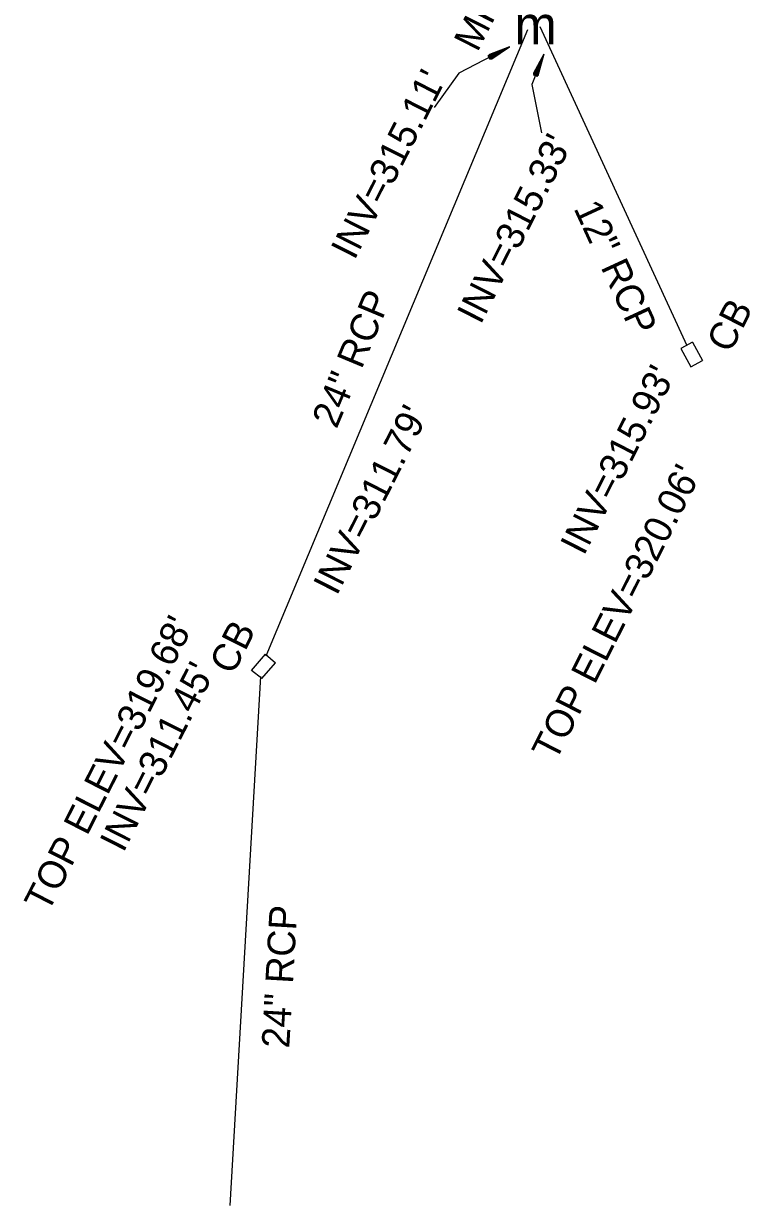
# Model space of a CAD drawing. Extents: x 1975859 to 1978323, y 778892 to 782836.
# Drawn here: x 1978070.4 to 1978175.3, y 782452.2 to 782622.9 of the extents above; entities that cross this region are included whole.
import ezdxf

# ---------------------------------------------------------------- set-up
doc = ezdxf.new("R2010")
doc.units = 0
for name, color, linetype in [('Exist Structure Minor Catch Basin', 7, 'Continuous'), ('Exist Structure Minor Catch Basin Text', 7, 'Continuous'), ('Exist Structure Minor Catch Basin Top Elevation', 7, 'Continuous'), ('Exist Structure Minor Pipes RCP 12 Inch', 7, 'Continuous'), ('Exist Structure Minor Pipes RCP 12 Inch Text', 7, 'Continuous'), ('Exist Structure Minor Pipes RCP 15 Inch Invert', 7, 'Continuous'), ('Exist Structure Minor Pipes RCP 24 Inch', 7, 'Continuous'), ('Exist Structure Minor Pipes RCP 24 Inch Invert', 7, 'Continuous'), ('Exist Structure Minor Pipes RCP 24 Inch Text', 7, 'Continuous'), ('Exist Structure Minor Storm Sewer Manhole CELL', 7, 'Continuous'), ('Exist Structure Minor Storm Sewer Manhole Text', 7, 'Continuous')]:
    doc.layers.add(name, color=color, linetype=linetype)

msp = doc.modelspace()

# ---------------------------------------------------------------- linework, layer by layer
at = {"layer": 'Exist Structure Minor Catch Basin'}
for p, q in [((1978167.01, 782576.9), (1978168.42, 782574.24)), ((1978104.79, 782528.33), (1978106.75, 782530.57))]:
    msp.add_line(p, q, dxfattribs=at)
for points in [[(1978166.97, 782576.86), (1978167.01, 782576.9), (1978165.3, 782575.99), (1978166.76, 782573.3), (1978168.42, 782574.24)], [(1978104.79, 782528.33), (1978103.31, 782529.46), (1978105.33, 782531.84), (1978106.75, 782530.57)]]:
    msp.add_lwpolyline(points, dxfattribs=at)
at = {"layer": 'Exist Structure Minor Pipes RCP 12 Inch'}
msp.add_line((1978144.94, 782622.47), (1978166.17, 782576.41), dxfattribs=at)
at = {"layer": 'Exist Structure Minor Pipes RCP 15 Inch Invert'}
for p, q in [((1978145.51, 782618.45), (1978143.81, 782614.09)), ((1978144.55, 782615.27), (1978144.06, 782615.46)), ((1978144.12, 782615.49), (1978144.42, 782615.66)), ((1978144.42, 782615.66), (1978144.17, 782615.42)), ((1978144.42, 782615.66), (1978144.25, 782615.38)), ((1978144.42, 782615.66), (1978144.36, 782615.34)), ((1978144.42, 782615.66), (1978144.52, 782615.33)), ((1978144.42, 782615.66), (1978144.46, 782615.3)), ((1978143.81, 782614.09), (1978145.18, 782607.13))]:
    msp.add_line(p, q, dxfattribs=at)
for points in [[(1978144.55, 782615.27), (1978144.72, 782615.45), (1978145.51, 782618.45), (1978144.05, 782615.71), (1978144.06, 782615.46)], [(1978144.55, 782615.43), (1978145.51, 782618.45), (1978144.55, 782615.27), (1978144.52, 782615.33), (1978144.55, 782615.43), (1978144.42, 782615.66), (1978144.16, 782615.58), (1978144.12, 782615.49), (1978144.06, 782615.46), (1978145.51, 782618.45), (1978144.16, 782615.58)], [(1978144.06, 782615.59), (1978145.51, 782618.45), (1978144.64, 782615.36)], [(1978145.44, 782618.3), (1978145.48, 782618.37), (1978145.46, 782618.27), (1978145.43, 782618.18), (1978145.44, 782618.28), (1978145.4, 782618.21), (1978145.36, 782618.12), (1978145.41, 782618.19), (1978145.4, 782618.1), (1978145.37, 782618.01), (1978145.38, 782618.1), (1978145.32, 782618.04), (1978145.28, 782617.96), (1978145.34, 782618.02), (1978145.34, 782617.92), (1978145.31, 782617.83), (1978145.31, 782617.93), (1978145.24, 782617.87), (1978145.2, 782617.79), (1978145.27, 782617.84), (1978145.29, 782617.74), (1978145.26, 782617.65), (1978145.24, 782617.75), (1978145.16, 782617.7), (1978145.12, 782617.62), (1978145.21, 782617.67), (1978145.23, 782617.56), (1978145.2, 782617.47), (1978145.17, 782617.58), (1978145.08, 782617.53), (1978145.04, 782617.45), (1978145.14, 782617.49), (1978145.17, 782617.38), (1978145.14, 782617.29), (1978145.1, 782617.41), (1978145, 782617.36), (1978144.96, 782617.28), (1978145.07, 782617.32), (1978145.12, 782617.2), (1978145.09, 782617.11), (1978145.03, 782617.23), (1978144.92, 782617.19), (1978144.88, 782617.11), (1978145, 782617.14), (1978145.06, 782617.03), (1978145.03, 782616.94), (1978144.97, 782617.06), (1978144.84, 782617.02), (1978144.8, 782616.94), (1978144.93, 782616.97), (1978145, 782616.85), (1978144.97, 782616.76), (1978144.9, 782616.88), (1978144.76, 782616.85), (1978144.72, 782616.77), (1978144.86, 782616.8), (1978144.95, 782616.67), (1978144.92, 782616.58), (1978144.83, 782616.71), (1978144.68, 782616.69), (1978144.64, 782616.6), (1978144.8, 782616.62), (1978144.89, 782616.49), (1978144.86, 782616.4), (1978144.76, 782616.53), (1978144.6, 782616.52), (1978144.56, 782616.43), (1978144.73, 782616.45), (1978144.83, 782616.31), (1978144.8, 782616.22), (1978144.7, 782616.36), (1978144.52, 782616.35), (1978144.48, 782616.26), (1978144.66, 782616.27), (1978144.78, 782616.13), (1978144.75, 782616.04), (1978144.63, 782616.19), (1978144.44, 782616.18), (1978144.4, 782616.09), (1978144.59, 782616.1), (1978144.72, 782615.95), (1978144.69, 782615.86), (1978144.56, 782616.01), (1978144.36, 782616.01), (1978144.32, 782615.92), (1978144.52, 782615.92), (1978144.66, 782615.78), (1978144.63, 782615.69), (1978144.49, 782615.84), (1978144.28, 782615.84), (1978144.24, 782615.75), (1978144.46, 782615.75), (1978144.61, 782615.6), (1978144.58, 782615.51), (1978144.42, 782615.66), (1978144.2, 782615.67)]]:
    msp.add_lwpolyline(points, dxfattribs=at)
at = {"layer": 'Exist Structure Minor Pipes RCP 24 Inch'}
for p, q in [((1978105.41, 782531.58), (1978143.2, 782622.04)), ((1978100.23, 782452.23), (1978104.64, 782528.59))]:
    msp.add_line(p, q, dxfattribs=at)
at = {"layer": 'Exist Structure Minor Pipes RCP 24 Inch Invert'}
for p, q in [((1978140.57, 782619.53), (1978133.25, 782615.75)), ((1978137.74, 782617.77), (1978137.5, 782618.24)), ((1978137.91, 782618.15), (1978137.55, 782618.14)), ((1978137.56, 782618.22), (1978137.91, 782618.15)), ((1978137.91, 782618.15), (1978137.59, 782618.06)), ((1978137.91, 782618.15), (1978137.65, 782617.95)), ((1978137.91, 782618.15), (1978137.7, 782617.86)), ((1978137.91, 782618.15), (1978137.76, 782617.83)), ((1978133.25, 782615.75), (1978129.7, 782610.75))]:
    msp.add_line(p, q, dxfattribs=at)
for points in [[(1978137.85, 782617.89), (1978140.57, 782619.53), (1978137.74, 782617.77), (1978137.76, 782617.83), (1978137.85, 782617.89), (1978137.91, 782618.15), (1978137.66, 782618.26), (1978137.56, 782618.22), (1978137.5, 782618.24), (1978140.57, 782619.53), (1978137.66, 782618.26)], [(1978137.74, 782617.77), (1978137.99, 782617.79), (1978140.57, 782619.53), (1978137.66, 782618.43), (1978137.5, 782618.24)], [(1978137.58, 782618.34), (1978140.57, 782619.53), (1978137.87, 782617.78)], [(1978140.41, 782619.45), (1978140.48, 782619.48), (1978140.41, 782619.43), (1978140.33, 782619.38), (1978140.4, 782619.44), (1978140.32, 782619.42), (1978140.24, 782619.38), (1978140.32, 782619.4), (1978140.25, 782619.33), (1978140.17, 782619.28), (1978140.24, 782619.35), (1978140.15, 782619.34), (1978140.07, 782619.31), (1978140.15, 782619.31), (1978140.09, 782619.24), (1978140.01, 782619.19), (1978140.07, 782619.27), (1978139.98, 782619.27), (1978139.89, 782619.23), (1978139.99, 782619.22), (1978139.93, 782619.14), (1978139.85, 782619.09), (1978139.9, 782619.18), (1978139.81, 782619.19), (1978139.72, 782619.16), (1978139.82, 782619.14), (1978139.77, 782619.04), (1978139.69, 782618.99), (1978139.74, 782619.1), (1978139.64, 782619.12), (1978139.55, 782619.08), (1978139.65, 782619.05), (1978139.61, 782618.95), (1978139.53, 782618.9), (1978139.57, 782619.01), (1978139.46, 782619.04), (1978139.38, 782619.01), (1978139.49, 782618.97), (1978139.45, 782618.85), (1978139.36, 782618.8), (1978139.4, 782618.92), (1978139.29, 782618.97), (1978139.21, 782618.93), (1978139.32, 782618.88), (1978139.28, 782618.75), (1978139.2, 782618.7), (1978139.24, 782618.84), (1978139.12, 782618.9), (1978139.03, 782618.86), (1978139.15, 782618.8), (1978139.12, 782618.66), (1978139.04, 782618.61), (1978139.07, 782618.75), (1978138.95, 782618.82), (1978138.86, 782618.78), (1978138.99, 782618.71), (1978138.96, 782618.56), (1978138.88, 782618.51), (1978138.9, 782618.67), (1978138.78, 782618.75), (1978138.69, 782618.71), (1978138.82, 782618.62), (1978138.8, 782618.46), (1978138.72, 782618.41), (1978138.74, 782618.58), (1978138.61, 782618.67), (1978138.52, 782618.64), (1978138.65, 782618.54), (1978138.64, 782618.37), (1978138.56, 782618.32), (1978138.57, 782618.49), (1978138.43, 782618.6), (1978138.35, 782618.56), (1978138.49, 782618.45), (1978138.48, 782618.27), (1978138.4, 782618.22), (1978138.4, 782618.41), (1978138.26, 782618.52), (1978138.18, 782618.49), (1978138.32, 782618.37), (1978138.32, 782618.17), (1978138.24, 782618.13), (1978138.24, 782618.32), (1978138.09, 782618.45), (1978138, 782618.41), (1978138.16, 782618.28), (1978138.16, 782618.08), (1978138.08, 782618.03), (1978138.07, 782618.24), (1978137.92, 782618.37), (1978137.83, 782618.34), (1978137.99, 782618.19), (1978138, 782617.98), (1978137.92, 782617.93), (1978137.91, 782618.15), (1978137.75, 782618.3)]]:
    msp.add_lwpolyline(points, dxfattribs=at)

# ---------------------------------------------------------------- texts
at = {"layer": 'Exist Structure Minor Catch Basin Text'}
for p in [(1978172.43, 782575.14), (1978100.64, 782528.69)]:
    msp.add_text('CB', height=4, rotation=63.1198, dxfattribs=at).set_placement(p)
at = {"layer": 'Exist Structure Minor Catch Basin Top Elevation'}
for s, p in [("TOP ELEV=320.06'", (1978147.2, 782516.19)), ("TOP ELEV=319.68'", (1978073.92, 782494.35))]:
    msp.add_text(s, height=4, rotation=63.1198, dxfattribs=at).set_placement(p)
at = {"layer": 'Exist Structure Minor Pipes RCP 12 Inch Text'}
msp.add_text('12" RCP', height=4, rotation=294.7523, dxfattribs=at).set_placement((1978149.77, 782596.22))
at = {"layer": 'Exist Structure Minor Pipes RCP 15 Inch Invert'}
for s, p in [("INV=315.33'", (1978136.38, 782579.3)), ("INV=315.93'", (1978151.3, 782545.92))]:
    msp.add_text(s, height=4, rotation=63.1198, dxfattribs=at).set_placement(p)
at = {"layer": 'Exist Structure Minor Pipes RCP 24 Inch Invert'}
for s, p in [("INV=315.11'", (1978118.18, 782588.6)), ("INV=311.79'", (1978115.62, 782540.15)), ("INV=311.45'", (1978084.8, 782503.05))]:
    msp.add_text(s, height=4, rotation=63.1198, dxfattribs=at).set_placement(p)
at = {"layer": 'Exist Structure Minor Pipes RCP 24 Inch Text'}
for rotation, p in [(67.3236, (1978115.59, 782564.25)), (86.6943, (1978108.75, 782474.86))]:
    msp.add_text('24" RCP', height=4, rotation=rotation, dxfattribs=at).set_placement(p)
at = {"layer": 'Exist Structure Minor Storm Sewer Manhole CELL'}
msp.add_text('m', height=5.5, dxfattribs=at).set_placement((1978141.27, 782619.91))
at = {"layer": 'Exist Structure Minor Storm Sewer Manhole Text'}
msp.add_text('MH', height=4, rotation=63.1198, dxfattribs=at).set_placement((1978135.93, 782618.65))

doc.saveas('drawing.dxf')
